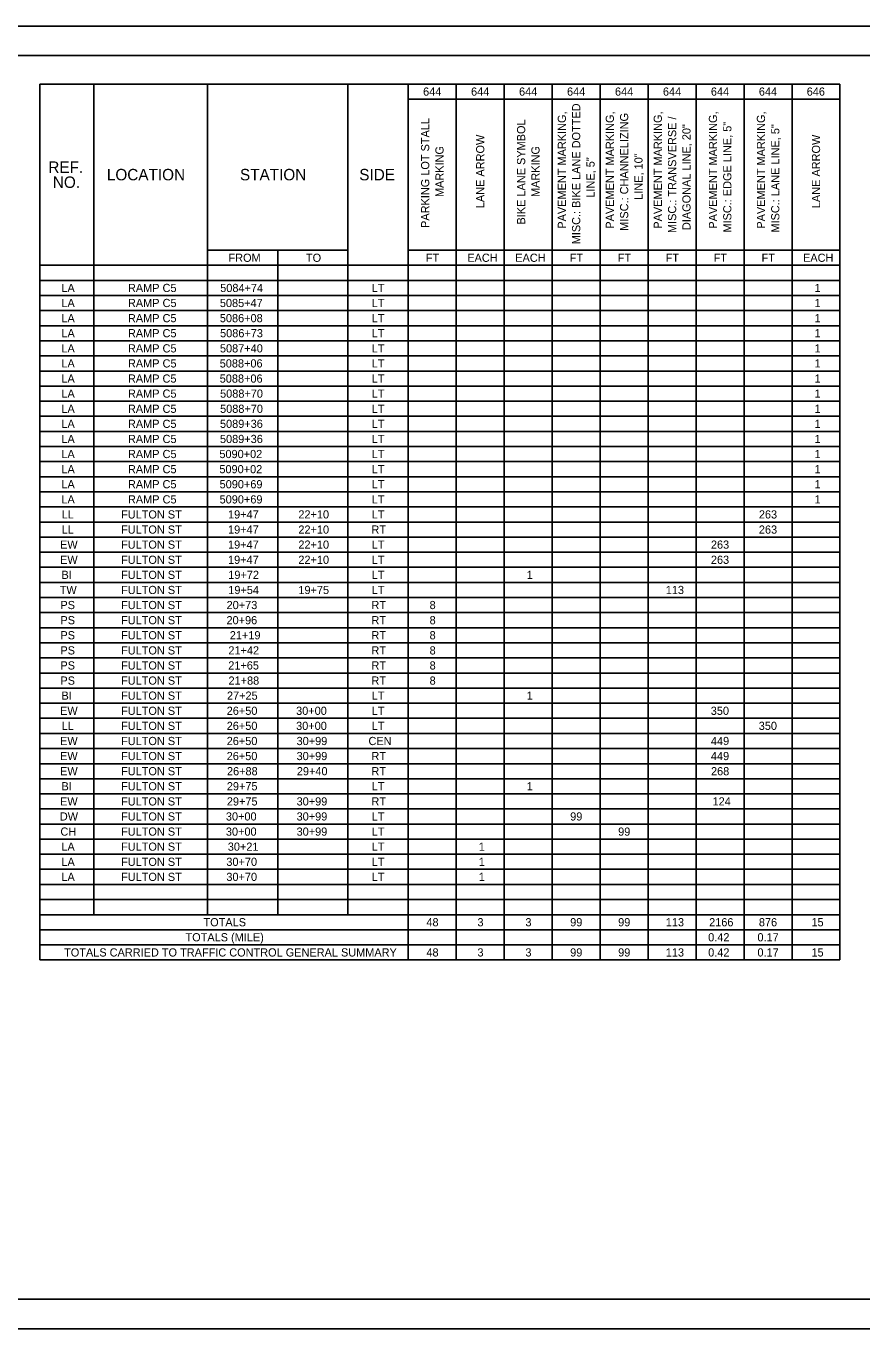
# Model space of a CAD drawing. Extents: x 1822205 to 1824724, y 710141 to 711863.
# Drawn here: x 1822785 to 1823491, y 710141 to 711241 of the extents above; entities that cross this region are included whole.
import ezdxf

# ---------------------------------------------------------------- set-up
doc = ezdxf.new("R2010")
doc.units = 0
for name, color, linetype in [('PM_P_Cells', 7, 'Continuous'), ('SH_Border', 7, 'Continuous'), ('SH_Cut_Line', 7, 'Continuous'), ('SH_Text', 7, 'Continuous')]:
    doc.layers.add(name, color=color, linetype=linetype)

msp = doc.modelspace()

# ---------------------------------------------------------------- linework, layer by layer
at = {"layer": 'PM_P_Cells'}
for p, q in [((1822797, 711192.5), (1823148.7, 711192.5)), ((1822797, 711192.5), (1822797, 710453)), ((1822842.7, 711192.5), (1822842.7, 710491.2)), ((1822938.7, 711192.5), (1822938.7, 710491.2)), ((1823057.2, 711192.5), (1823057.2, 710491.2)), ((1823108.2, 711192.5), (1823108.2, 710453)), ((1823148.7, 711192.5), (1823229.7, 711192.5)), ((1823148.7, 711192.5), (1823148.7, 710453)), ((1823189.2, 711192.5), (1823189.2, 710453)), ((1823229.7, 711192.5), (1823472.7, 711192.5)), ((1823229.7, 711192.5), (1823229.7, 710453)), ((1823270.2, 711192.5), (1823270.2, 710453)), ((1823310.7, 711192.5), (1823310.7, 710453)), ((1823351.2, 711192.5), (1823351.2, 710453)), ((1823391.7, 711192.5), (1823391.7, 710453)), ((1823432.2, 711192.5), (1823432.2, 710453)), ((1823472.7, 711192.5), (1823472.7, 710453)), ((1823108.2, 711179.7), (1823472.7, 711179.7)), ((1822938.7, 711052.2), (1823057.2, 711052.2)), ((1822998, 711052.2), (1822998, 710491.2)), ((1823108.2, 711052.2), (1823472.7, 711052.2)), ((1822797, 711039.5), (1823472.7, 711039.5)), ((1822797, 711026.7), (1823472.7, 711026.7)), ((1822797, 711014), (1823472.7, 711014)), ((1822797, 711001.2), (1823472.7, 711001.2)), ((1822797, 710988.5), (1823472.7, 710988.5)), ((1822797, 710975.7), (1823472.7, 710975.7)), ((1822797, 710963), (1823472.7, 710963)), ((1822797, 710950.2), (1823472.7, 710950.2)), ((1822797, 710937.5), (1823472.7, 710937.5)), ((1822797, 710924.7), (1823472.7, 710924.7)), ((1822797, 710912), (1823472.7, 710912)), ((1822797, 710899.2), (1823472.7, 710899.2)), ((1822797, 710886.5), (1823472.7, 710886.5)), ((1822797, 710873.7), (1823472.7, 710873.7)), ((1822797, 710861), (1823472.7, 710861)), ((1822797, 710848.2), (1823472.7, 710848.2)), ((1822797, 710835.5), (1823472.7, 710835.5)), ((1822797, 710822.7), (1823472.7, 710822.7)), ((1822797, 710810), (1823472.7, 710810)), ((1822797, 710797.2), (1823472.7, 710797.2)), ((1822797, 710784.5), (1823472.7, 710784.5)), ((1822797, 710771.7), (1823472.7, 710771.7)), ((1822797, 710759), (1823472.7, 710759)), ((1822797, 710746.2), (1823472.7, 710746.2)), ((1822797, 710733.5), (1823472.7, 710733.5)), ((1822797, 710720.7), (1823472.7, 710720.7)), ((1822797, 710708), (1823472.7, 710708)), ((1822797, 710695.2), (1823472.7, 710695.2)), ((1822797, 710682.5), (1823472.7, 710682.5)), ((1822797, 710669.7), (1823472.7, 710669.7)), ((1822797, 710657), (1823472.7, 710657)), ((1822797, 710644.2), (1823472.7, 710644.2)), ((1822797, 710631.5), (1823472.7, 710631.5)), ((1822797, 710618.7), (1823472.7, 710618.7)), ((1822797, 710606), (1823472.7, 710606)), ((1822797, 710593.2), (1823472.7, 710593.2)), ((1822797, 710580.5), (1823472.7, 710580.5)), ((1822797, 710567.7), (1823472.7, 710567.7)), ((1822797, 710555), (1823472.7, 710555)), ((1822797, 710542.2), (1823472.7, 710542.2)), ((1822797, 710529.5), (1823472.7, 710529.5)), ((1822797, 710516.7), (1823472.7, 710516.7)), ((1822797, 710504), (1823472.7, 710504)), ((1822797, 710491.2), (1823472.7, 710491.2)), ((1822797, 710478.5), (1823472.7, 710478.5)), ((1822797, 710465.7), (1823472.7, 710465.7)), ((1822797, 710453), (1823472.7, 710453))]:
    msp.add_line(p, q, dxfattribs=at)
at = {"layer": 'SH_Border'}
msp.add_lwpolyline([(1822441.4, 711216.5), (1824016.4, 711216.5), (1824016.4, 710166.5), (1822441.4, 710166.5)], close=True, dxfattribs=at)
at = {"layer": 'SH_Cut_Line'}
msp.add_lwpolyline([(1822341.4, 710141.5), (1824041.4, 710141.5), (1824041.4, 711241.5), (1822341.4, 711241.5)], close=True, dxfattribs=at)
at = {"layer": 'SH_Text'}
msp.add_line((1822867.1, 710166.5), (1823966.4, 710166.5), dxfattribs=at)

# ---------------------------------------------------------------- texts
at = {"layer": 'PM_P_Cells'}
for s, height, p in [('644', 6.9, (1823120.7, 711182.7)), ('644', 6.9, (1823161.2, 711182.7)), ('644', 6.9, (1823201.7, 711182.7)), ('644', 6.9, (1823242.2, 711182.7)), ('644', 6.9, (1823282.7, 711182.7)), ('644', 6.9, (1823323.2, 711182.7)), ('644', 6.9, (1823363.7, 711182.7)), ('644', 6.9, (1823404.2, 711182.7)), ('646', 6.9, (1823444.6, 711182.7)), ('REF.', 9.66, (1822804.3, 711117.5)), ('LOCATION', 9.66, (1822853.7, 711111.2)), ('STATION', 9.66, (1822966.1, 711111.2)), ('SIDE', 9.66, (1823066.8, 711111.2)), ('NO.', 9.66, (1822808.1, 711104.8)), ('FROM', 6.9, (1822956.4, 711042.4)), ('TO', 6.9, (1823021.8, 711042.4)), ('FT', 6.9, (1823123, 711042.4)), ('EACH', 6.9, (1823158, 711042.4)), ('EACH', 6.9, (1823198.5, 711042.4)), ('FT', 6.9, (1823244.5, 711042.4)), ('FT', 6.9, (1823285, 711042.4)), ('FT', 6.9, (1823325.5, 711042.4)), ('FT', 6.9, (1823366, 711042.4)), ('FT', 6.9, (1823406.5, 711042.4)), ('EACH', 6.9, (1823441.5, 711042.4)), ('LA', 6.9, (1822815.3, 711016.9)), ('RAMP C5', 6.9, (1822871.5, 711016.9)), ('5084+74', 6.9, (1822949.4, 711016.9)), ('LT', 6.9, (1823077.3, 711016.9)), ('1', 6.9, (1823451.2, 711016.9)), ('LA', 6.9, (1822815.3, 711004.2)), ('RAMP C5', 6.9, (1822871.5, 711004.2)), ('5085+47', 6.9, (1822949.1, 711004.2)), ('LT', 6.9, (1823077.3, 711004.2)), ('1', 6.9, (1823451.2, 711004.2)), ('LA', 6.9, (1822815.3, 710991.4)), ('RAMP C5', 6.9, (1822871.5, 710991.4)), ('5086+08', 6.9, (1822949.1, 710991.4)), ('LT', 6.9, (1823077.3, 710991.4)), ('1', 6.9, (1823451.2, 710991.4)), ('LA', 6.9, (1822815.3, 710978.7)), ('RAMP C5', 6.9, (1822871.5, 710978.7)), ('5086+73', 6.9, (1822949.3, 710978.7)), ('LT', 6.9, (1823077.3, 710978.7)), ('1', 6.9, (1823451.2, 710978.7)), ('LA', 6.9, (1822815.3, 710965.9)), ('RAMP C5', 6.9, (1822871.5, 710965.9)), ('5087+40', 6.9, (1822949.2, 710965.9)), ('LT', 6.9, (1823077.3, 710965.9)), ('1', 6.9, (1823451.2, 710965.9)), ('LA', 6.9, (1822815.3, 710953.2)), ('RAMP C5', 6.9, (1822871.5, 710953.2)), ('5088+06', 6.9, (1822949, 710953.2)), ('LT', 6.9, (1823077.3, 710953.2)), ('1', 6.9, (1823451.2, 710953.2)), ('LA', 6.9, (1822815.3, 710940.4)), ('RAMP C5', 6.9, (1822871.5, 710940.4)), ('5088+06', 6.9, (1822949, 710940.4)), ('LT', 6.9, (1823077.3, 710940.4)), ('1', 6.9, (1823451.2, 710940.4)), ('LA', 6.9, (1822815.3, 710927.7)), ('RAMP C5', 6.9, (1822871.5, 710927.7)), ('5088+70', 6.9, (1822949.3, 710927.7)), ('LT', 6.9, (1823077.3, 710927.7)), ('1', 6.9, (1823451.2, 710927.7)), ('LA', 6.9, (1822815.3, 710914.9)), ('RAMP C5', 6.9, (1822871.5, 710914.9)), ('5088+70', 6.9, (1822949.3, 710914.9)), ('LT', 6.9, (1823077.3, 710914.9)), ('1', 6.9, (1823451.2, 710914.9)), ('LA', 6.9, (1822815.3, 710902.2)), ('RAMP C5', 6.9, (1822871.5, 710902.2)), ('5089+36', 6.9, (1822949.2, 710902.2)), ('LT', 6.9, (1823077.3, 710902.2)), ('1', 6.9, (1823451.2, 710902.2)), ('LA', 6.9, (1822815.3, 710889.4)), ('RAMP C5', 6.9, (1822871.5, 710889.4)), ('5089+36', 6.9, (1822949.2, 710889.4)), ('LT', 6.9, (1823077.3, 710889.4)), ('1', 6.9, (1823451.2, 710889.4)), ('LA', 6.9, (1822815.3, 710876.7)), ('RAMP C5', 6.9, (1822871.5, 710876.7)), ('5090+02', 6.9, (1822948.7, 710876.7)), ('LT', 6.9, (1823077.3, 710876.7)), ('1', 6.9, (1823451.2, 710876.7)), ('LA', 6.9, (1822815.3, 710863.9)), ('RAMP C5', 6.9, (1822871.5, 710863.9)), ('5090+02', 6.9, (1822948.7, 710863.9)), ('LT', 6.9, (1823077.3, 710863.9)), ('1', 6.9, (1823451.2, 710863.9)), ('LA', 6.9, (1822815.3, 710851.2)), ('RAMP C5', 6.9, (1822871.5, 710851.2)), ('5090+69', 6.9, (1822948.9, 710851.2)), ('LT', 6.9, (1823077.3, 710851.2)), ('1', 6.9, (1823451.2, 710851.2)), ('LA', 6.9, (1822815.3, 710838.4)), ('RAMP C5', 6.9, (1822871.5, 710838.4)), ('5090+69', 6.9, (1822948.9, 710838.4)), ('LT', 6.9, (1823077.3, 710838.4)), ('1', 6.9, (1823451.2, 710838.4)), ('LL', 6.9, (1822815.5, 710825.7)), ('FULTON ST', 6.9, (1822865.7, 710825.7)), ('19+47', 6.9, (1822956, 710825.7)), ('22+10', 6.9, (1823015.4, 710825.7)), ('LT', 6.9, (1823077.3, 710825.7)), ('263', 6.9, (1823404.2, 710825.7)), ('LL', 6.9, (1822815.5, 710812.9)), ('FULTON ST', 6.9, (1822865.7, 710812.9)), ('19+47', 6.9, (1822956, 710812.9)), ('22+10', 6.9, (1823015.4, 710812.9)), ('RT', 6.9, (1823077.1, 710812.9)), ('263', 6.9, (1823404.2, 710812.9)), ('EW', 6.9, (1822814.2, 710800.2)), ('FULTON ST', 6.9, (1822865.7, 710800.2)), ('19+47', 6.9, (1822956, 710800.2)), ('22+10', 6.9, (1823015.4, 710800.2)), ('LT', 6.9, (1823077.3, 710800.2)), ('263', 6.9, (1823363.7, 710800.2)), ('EW', 6.9, (1822814.2, 710787.4)), ('FULTON ST', 6.9, (1822865.7, 710787.4)), ('19+47', 6.9, (1822956, 710787.4)), ('22+10', 6.9, (1823015.4, 710787.4)), ('LT', 6.9, (1823077.3, 710787.4)), ('263', 6.9, (1823363.7, 710787.4)), ('BI', 6.9, (1822815.4, 710774.7)), ('FULTON ST', 6.9, (1822865.7, 710774.7)), ('19+72', 6.9, (1822956.2, 710774.7)), ('LT', 6.9, (1823077.3, 710774.7)), ('1', 6.9, (1823208.2, 710774.7)), ('TW', 6.9, (1822813.9, 710761.9)), ('FULTON ST', 6.9, (1822865.7, 710761.9)), ('19+54', 6.9, (1822956.2, 710761.9)), ('19+75', 6.9, (1823015.4, 710761.9)), ('LT', 6.9, (1823077.3, 710761.9)), ('113', 6.9, (1823325.6, 710761.9)), ('PS', 6.9, (1822814.5, 710749.2)), ('FULTON ST', 6.9, (1822865.7, 710749.2)), ('20+73', 6.9, (1822954.8, 710749.2)), ('RT', 6.9, (1823077.1, 710749.2)), ('8', 6.9, (1823126.2, 710749.2)), ('PS', 6.9, (1822814.5, 710736.4)), ('FULTON ST', 6.9, (1822865.7, 710736.4)), ('20+96', 6.9, (1822954.7, 710736.4)), ('RT', 6.9, (1823077.1, 710736.4)), ('8', 6.9, (1823126.2, 710736.4)), ('PS', 6.9, (1822814.5, 710723.7)), ('FULTON ST', 6.9, (1822865.7, 710723.7)), ('21+19', 6.9, (1822957.5, 710723.7)), ('RT', 6.9, (1823077.1, 710723.7)), ('8', 6.9, (1823126.2, 710723.7)), ('PS', 6.9, (1822814.5, 710710.9)), ('FULTON ST', 6.9, (1822865.7, 710710.9)), ('21+42', 6.9, (1822956.3, 710710.9)), ('RT', 6.9, (1823077.1, 710710.9)), ('8', 6.9, (1823126.2, 710710.9)), ('PS', 6.9, (1822814.5, 710698.2)), ('FULTON ST', 6.9, (1822865.7, 710698.2)), ('21+65', 6.9, (1822956.2, 710698.2)), ('RT', 6.9, (1823077.1, 710698.2)), ('8', 6.9, (1823126.2, 710698.2)), ('PS', 6.9, (1822814.5, 710685.4)), ('FULTON ST', 6.9, (1822865.7, 710685.4)), ('21+88', 6.9, (1822956.4, 710685.4)), ('RT', 6.9, (1823077.1, 710685.4)), ('8', 6.9, (1823126.2, 710685.4)), ('BI', 6.9, (1822815.4, 710672.7)), ('FULTON ST', 6.9, (1822865.7, 710672.7)), ('27+25', 6.9, (1822955.1, 710672.7)), ('LT', 6.9, (1823077.3, 710672.7)), ('1', 6.9, (1823208.2, 710672.7)), ('EW', 6.9, (1822814.2, 710659.9)), ('FULTON ST', 6.9, (1822865.7, 710659.9)), ('26+50', 6.9, (1822954.9, 710659.9)), ('30+00', 6.9, (1823013.5, 710659.9)), ('LT', 6.9, (1823077.3, 710659.9)), ('350', 6.9, (1823363.6, 710659.9)), ('LL', 6.9, (1822815.5, 710647.2)), ('FULTON ST', 6.9, (1822865.7, 710647.2)), ('26+50', 6.9, (1822954.9, 710647.2)), ('30+00', 6.9, (1823013.5, 710647.2)), ('LT', 6.9, (1823077.3, 710647.2)), ('350', 6.9, (1823404.1, 710647.2)), ('EW', 6.9, (1822814.2, 710634.4)), ('FULTON ST', 6.9, (1822865.7, 710634.4)), ('26+50', 6.9, (1822954.9, 710634.4)), ('30+99', 6.9, (1823013.9, 710634.4)), ('CEN', 6.9, (1823074.6, 710634.4)), ('449', 6.9, (1823363.7, 710634.4)), ('EW', 6.9, (1822814.2, 710621.7)), ('FULTON ST', 6.9, (1822865.7, 710621.7)), ('26+50', 6.9, (1822954.9, 710621.7)), ('30+99', 6.9, (1823013.9, 710621.7)), ('RT', 6.9, (1823077.1, 710621.7)), ('449', 6.9, (1823363.7, 710621.7)), ('EW', 6.9, (1822814.2, 710608.9)), ('FULTON ST', 6.9, (1822865.7, 710608.9)), ('26+88', 6.9, (1822955.1, 710608.9)), ('29+40', 6.9, (1823014.1, 710608.9)), ('RT', 6.9, (1823077.1, 710608.9)), ('268', 6.9, (1823363.8, 710608.9)), ('BI', 6.9, (1822815.4, 710596.2)), ('FULTON ST', 6.9, (1822865.7, 710596.2)), ('29+75', 6.9, (1822955, 710596.2)), ('LT', 6.9, (1823077.3, 710596.2)), ('1', 6.9, (1823208.2, 710596.2)), ('EW', 6.9, (1822814.2, 710583.4)), ('FULTON ST', 6.9, (1822865.7, 710583.4)), ('29+75', 6.9, (1822955, 710583.4)), ('30+99', 6.9, (1823013.9, 710583.4)), ('RT', 6.9, (1823077.1, 710583.4)), ('124', 6.9, (1823365.1, 710583.4)), ('DW', 6.9, (1822814, 710570.7)), ('FULTON ST', 6.9, (1822865.7, 710570.7)), ('30+00', 6.9, (1822954.2, 710570.7)), ('30+99', 6.9, (1823013.9, 710570.7)), ('LT', 6.9, (1823077.3, 710570.7)), ('99', 6.9, (1823244.9, 710570.7)), ('CH', 6.9, (1822814.5, 710557.9)), ('FULTON ST', 6.9, (1822865.7, 710557.9)), ('30+00', 6.9, (1822954.2, 710557.9)), ('30+99', 6.9, (1823013.9, 710557.9)), ('LT', 6.9, (1823077.3, 710557.9)), ('99', 6.9, (1823285.4, 710557.9)), ('LA', 6.9, (1822815.3, 710545.2)), ('FULTON ST', 6.9, (1822865.7, 710545.2)), ('30+21', 6.9, (1822955.8, 710545.2)), ('LT', 6.9, (1823077.3, 710545.2)), ('1', 6.9, (1823167.7, 710545.2)), ('LA', 6.9, (1822815.3, 710532.4)), ('FULTON ST', 6.9, (1822865.7, 710532.4)), ('30+70', 6.9, (1822954.6, 710532.4)), ('LT', 6.9, (1823077.3, 710532.4)), ('1', 6.9, (1823167.7, 710532.4)), ('LA', 6.9, (1822815.3, 710519.7)), ('FULTON ST', 6.9, (1822865.7, 710519.7)), ('30+70', 6.9, (1822954.6, 710519.7)), ('LT', 6.9, (1823077.3, 710519.7)), ('1', 6.9, (1823167.7, 710519.7)), ('TOTALS', 6.9, (1822935.3, 710481.4)), ('48', 6.9, (1823123.5, 710481.4)), ('3', 6.9, (1823166.6, 710481.4)), ('3', 6.9, (1823207.1, 710481.4)), ('99', 6.9, (1823244.9, 710481.4)), ('99', 6.9, (1823285.4, 710481.4)), ('113', 6.9, (1823325.6, 710481.4)), ('2166', 6.9, (1823362.2, 710481.4)), ('876', 6.9, (1823404.2, 710481.4)), ('15', 6.9, (1823448.6, 710481.4)), ('TOTALS (MILE)', 6.9, (1822920.1, 710468.7)), ('0.42', 6.9, (1823361.4, 710468.7)), ('0.17', 6.9, (1823403, 710468.7)), ('TOTALS CARRIED TO TRAFFIC CONTROL GENERAL SUMMARY', 6.9, (1822817.6, 710455.9)), ('48', 6.9, (1823123.5, 710455.9)), ('3', 6.9, (1823166.6, 710455.9)), ('3', 6.9, (1823207.1, 710455.9)), ('99', 6.9, (1823244.9, 710455.9)), ('99', 6.9, (1823285.4, 710455.9)), ('113', 6.9, (1823325.6, 710455.9)), ('0.42', 6.9, (1823361.4, 710455.9)), ('0.17', 6.9, (1823403, 710455.9)), ('15', 6.9, (1823448.6, 710455.9))]:
    msp.add_text(s, height=height, dxfattribs=at).set_placement(p)
for s, p in [('MISC.: BIKE LANE DOTTED', (1823253.4, 711057.2)), ('PARKING LOT STALL', (1823125.9, 711071)), ('BIKE LANE SYMBOL', (1823206.9, 711073.9)), ('PAVEMENT MARKING,', (1823241.3, 711070.4)), ('PAVEMENT MARKING,', (1823281.8, 711070.4)), ('MISC.: CHANNELIZING', (1823293.9, 711068.6)), ('PAVEMENT MARKING,', (1823322.3, 711070.4)), ('MISC.: TRANSVERSE /', (1823334.4, 711066.7)), ('PAVEMENT MARKING,', (1823368.9, 711070.4)), ('PAVEMENT MARKING,', (1823409.4, 711070.4)), ('DIAGONAL LINE, 20"', (1823346.5, 711069.2)), ('MISC.: EDGE LINE, 5"', (1823381, 711067.1)), ('MISC.: LANE LINE, 5"', (1823421.5, 711067.1)), ('MARKING', (1823138, 711097.1)), ('LANE ARROW', (1823172.4, 711087.7)), ('MARKING', (1823219, 711097.1)), ('LANE ARROW', (1823455.9, 711087.7)), ('LINE, 5"', (1823265.5, 711096.6)), ('LINE, 10"', (1823306, 711094.8))]:
    msp.add_text(s, height=6.9, rotation=90, dxfattribs=at).set_placement(p)

doc.saveas('drawing.dxf')
